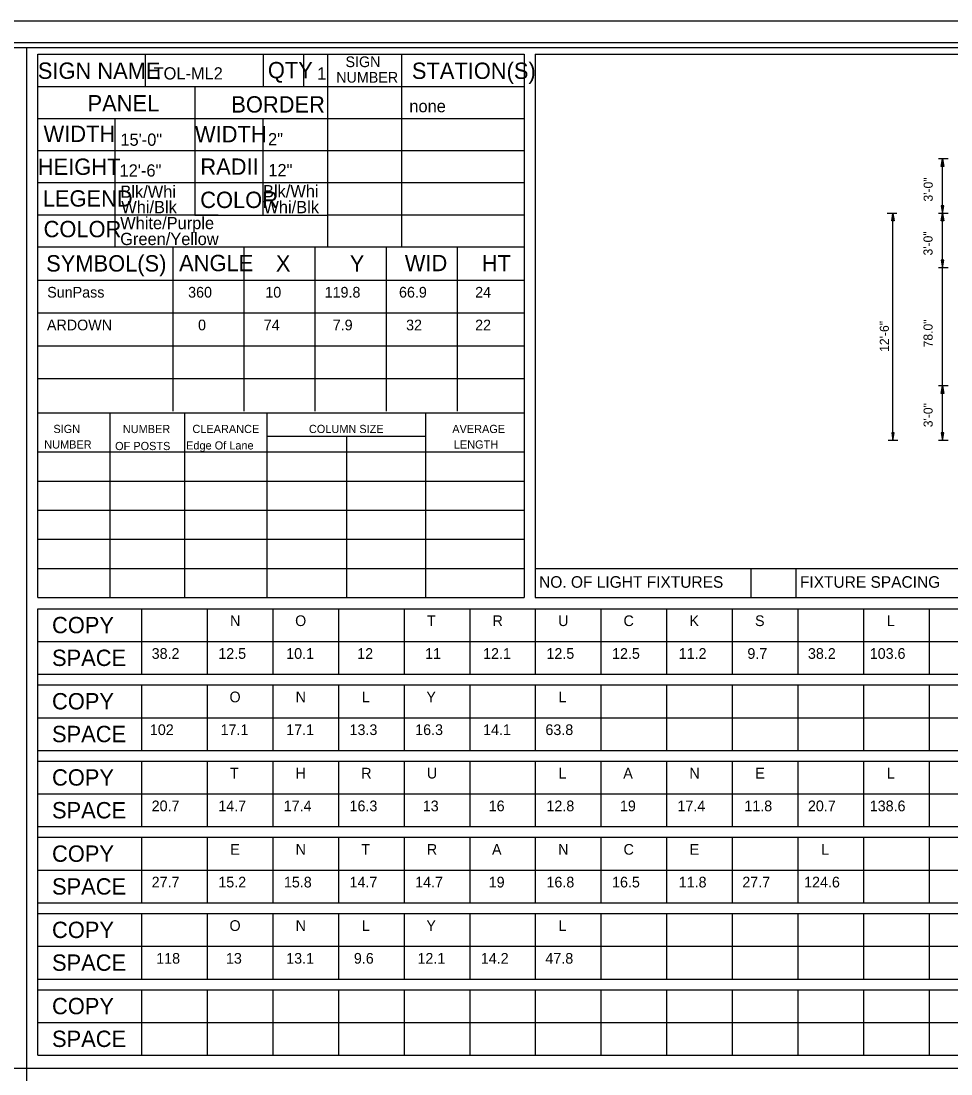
# Model space of a CAD drawing. Extents: x 119523 to 121850, y -23542 to -19972.
# Drawn here: x 120684 to 121298, y -22723 to -22028 of the extents above; entities that cross this region are included whole.
import ezdxf

# ---------------------------------------------------------------- set-up
doc = ezdxf.new("R2010")
doc.units = 0
for name, color, linetype in [('GSDims', 7, 'Continuous'), ('GSSign', 7, 'Continuous'), ('PlotBorder_dp', 7, 'Continuous'), ('SheetBorder_dp', 7, 'Continuous'), ('SheetLinesMisc2_dp', 7, 'Continuous'), ('TextMinor', 7, 'Continuous')]:
    doc.layers.add(name, color=color, linetype=linetype)

msp = doc.modelspace()

# ---------------------------------------------------------------- linework, layer by layer
at = {"layer": 'GSDims'}
for p, q in [((121296.16, -22118.76), (121289.91, -22118.76)), ((121292.41, -22154.76), (121292.41, -22118.76)), ((121296.16, -22118.76), (121296.16, -22118.76)), ((121262.22, -22154.76), (121255.97, -22154.76)), ((121259.74, -22304.76), (121259.74, -22154.76)), ((121296.16, -22154.76), (121289.91, -22154.76)), ((121292.41, -22190.76), (121292.41, -22154.76)), ((121296.16, -22154.76), (121296.16, -22154.76)), ((121296.16, -22190.76), (121289.91, -22190.76)), ((121292.41, -22268.76), (121292.41, -22190.76)), ((121296.16, -22268.76), (121289.91, -22268.76)), ((121292.41, -22304.76), (121292.41, -22268.76)), ((121262.87, -22304.76), (121256.62, -22304.76)), ((121296.16, -22304.76), (121289.91, -22304.76))]:
    msp.add_line(p, q, dxfattribs=at)
for points in [[(121292.41, -22118.76), (121293.25, -22123.76), (121291.58, -22123.76)], [(121292.41, -22154.76), (121293.25, -22149.76), (121291.58, -22149.76)], [(121259.74, -22154.76), (121260.57, -22159.76), (121258.91, -22159.76)], [(121292.41, -22154.76), (121293.25, -22159.76), (121291.58, -22159.76)], [(121292.41, -22190.76), (121293.25, -22185.76), (121291.58, -22185.76)], [(121292.41, -22268.76), (121293.25, -22273.76), (121291.58, -22273.76)], [(121259.74, -22304.76), (121260.57, -22299.76), (121258.91, -22299.76)], [(121292.41, -22304.76), (121293.25, -22299.76), (121291.58, -22299.76)]]:
    msp.add_lwpolyline(points, close=True, dxfattribs=at)
at = {"layer": 'PlotBorder_dp'}
msp.add_lwpolyline([(119522.87, -23522.86), (121850.2, -23522.86), (121850.2, -22027.72), (119522.87, -22027.72)], close=True, dxfattribs=at)
at = {"layer": 'SheetBorder_dp'}
msp.add_line((119600.45, -22041.83), (121772.62, -22041.83), dxfattribs=at)
at = {"layer": 'SheetLinesMisc2_dp'}
for p, q in [((119604.34, -22045.17), (121770.65, -22045.17)), ((120687.5, -22045.17), (120687.5, -23393.68)), ((120694.89, -22408.55), (120694.89, -22049.67)), ((120694.89, -22049.67), (121016.1, -22049.67)), ((120765.7, -22049.67), (120765.7, -22070.86)), ((120843.77, -22049.67), (120843.77, -22070.86)), ((120870.45, -22049.67), (120870.45, -22070.86)), ((120886.34, -22049.67), (120886.34, -22176.86)), ((120935.22, -22049.67), (120935.22, -22176.86)), ((121016.1, -22049.67), (121016.1, -22408.55)), ((121023.51, -22049.66), (121760.29, -22049.66)), ((121023.51, -22049.66), (121023.51, -22408.55)), ((120694.89, -22070.86), (121016.1, -22070.86)), ((120798.7, -22070.86), (120798.7, -22155.88)), ((120694.89, -22092.06), (121016.1, -22092.06)), ((120745.65, -22092.06), (120745.65, -22176.86)), ((120843.5, -22092.29), (120843.5, -22155.88)), ((120694.89, -22113.26), (121016.1, -22113.26)), ((120694.89, -22134.46), (121016.1, -22134.46)), ((120694.89, -22155.66), (120814.02, -22155.66)), ((120798.7, -22155.88), (120886.34, -22155.88)), ((120886.34, -22155.66), (121016.1, -22155.66)), ((120694.89, -22176.86), (121016.1, -22176.86)), ((120784.1, -22177.28), (120784.1, -22285.5)), ((120831.03, -22177.28), (120831.03, -22285.5)), ((120877.96, -22177.28), (120877.96, -22285.5)), ((120924.89, -22177.28), (120924.89, -22285.5)), ((120971.83, -22177.28), (120971.83, -22285.5)), ((120694.96, -22198.92), (121016.1, -22198.92)), ((120694.96, -22220.57), (121016.1, -22220.57)), ((120694.96, -22242.21), (121016.1, -22242.21)), ((120694.96, -22263.86), (121016.1, -22263.86)), ((120694.89, -22286.54), (121016.1, -22286.54)), ((120742.55, -22286.54), (120742.55, -22408.55)), ((120791.83, -22286.54), (120791.83, -22408.55)), ((120846.22, -22286.54), (120846.22, -22408.55)), ((120950.97, -22286.54), (120950.97, -22408.55)), ((120846.22, -22302.06), (120950.9, -22302.06)), ((120898.81, -22302.06), (120898.81, -22408.55)), ((120694.89, -22312.41), (121016.1, -22312.41)), ((120694.89, -22331.63), (121016.1, -22331.63)), ((120694.89, -22350.86), (121016.1, -22350.86)), ((120694.89, -22370.09), (121016.1, -22370.09)), ((120694.89, -22389.32), (121016.1, -22389.32)), ((121023.51, -22389.32), (121760.29, -22389.32)), ((121165.82, -22389.32), (121165.82, -22408.55)), ((121195.64, -22389.32), (121195.64, -22408.55)), ((120694.89, -22408.55), (121016.1, -22408.55)), ((121023.51, -22408.55), (121760.29, -22408.55)), ((120694.9, -22710.93), (120694.9, -22415.94)), ((120694.9, -22415.94), (121760.29, -22415.94)), ((120763.48, -22415.94), (120763.48, -22459.23)), ((120806.83, -22415.94), (120806.83, -22459.23)), ((120850.15, -22415.94), (120850.15, -22459.23)), ((120893.49, -22415.94), (120893.49, -22459.23)), ((120936.85, -22415.94), (120936.85, -22459.23)), ((120980.18, -22415.94), (120980.18, -22459.23)), ((121023.51, -22415.94), (121023.51, -22459.23)), ((121066.86, -22415.94), (121066.86, -22459.23)), ((121110.2, -22415.94), (121110.2, -22459.23)), ((121153.54, -22415.94), (121153.54, -22459.23)), ((121196.89, -22415.94), (121196.89, -22459.23)), ((121240.21, -22415.94), (121240.21, -22459.23)), ((121283.56, -22415.94), (121283.56, -22459.23)), ((120694.9, -22437.58), (121760.29, -22437.58)), ((120694.9, -22459.23), (121760.29, -22459.23)), ((120694.9, -22466.29), (121760.29, -22466.29)), ((120763.48, -22466.29), (120763.48, -22509.57)), ((120806.83, -22466.29), (120806.83, -22509.57)), ((120850.15, -22466.29), (120850.15, -22509.57)), ((120893.49, -22466.29), (120893.49, -22509.57)), ((120936.85, -22466.29), (120936.85, -22509.57)), ((120980.18, -22466.29), (120980.18, -22509.57)), ((121023.51, -22466.29), (121023.51, -22509.57)), ((121066.86, -22466.29), (121066.86, -22509.57)), ((121110.2, -22466.29), (121110.2, -22509.57)), ((121153.54, -22466.29), (121153.54, -22509.57)), ((121196.89, -22466.29), (121196.89, -22509.57)), ((121240.21, -22466.29), (121240.21, -22509.57)), ((121283.56, -22466.29), (121283.56, -22509.57)), ((120694.9, -22487.94), (121760.29, -22487.92)), ((120694.9, -22509.57), (121760.29, -22509.57)), ((120694.9, -22516.62), (121760.29, -22516.62)), ((120763.48, -22516.62), (120763.48, -22559.91)), ((120806.83, -22516.62), (120806.83, -22559.91)), ((120850.15, -22516.62), (120850.15, -22559.91)), ((120893.49, -22516.62), (120893.49, -22559.91)), ((120936.85, -22516.62), (120936.85, -22559.91)), ((120980.18, -22516.62), (120980.18, -22559.91)), ((121023.51, -22516.62), (121023.51, -22559.91)), ((121066.86, -22516.62), (121066.86, -22559.91)), ((121110.2, -22516.62), (121110.2, -22559.91)), ((121153.54, -22516.62), (121153.54, -22559.91)), ((121196.89, -22516.62), (121196.89, -22559.91)), ((121240.21, -22516.62), (121240.21, -22559.91)), ((121283.56, -22516.62), (121283.56, -22559.91)), ((120694.9, -22538.27), (121760.29, -22538.27)), ((120694.9, -22559.91), (121760.29, -22559.91)), ((120694.9, -22566.96), (121760.29, -22566.96)), ((120763.48, -22566.96), (120763.48, -22610.25)), ((120806.83, -22566.96), (120806.83, -22610.25)), ((120850.15, -22566.96), (120850.15, -22610.25)), ((120893.49, -22566.96), (120893.49, -22610.25)), ((120936.85, -22566.96), (120936.85, -22610.25)), ((120980.18, -22566.96), (120980.18, -22610.25)), ((121023.51, -22566.96), (121023.51, -22610.25)), ((121066.86, -22566.96), (121066.86, -22610.25)), ((121110.2, -22566.96), (121110.2, -22610.25)), ((121153.54, -22566.96), (121153.54, -22610.25)), ((121196.89, -22566.96), (121196.89, -22610.25)), ((121240.21, -22566.96), (121240.21, -22610.25)), ((121283.56, -22566.96), (121283.56, -22610.25)), ((120694.9, -22588.61), (121760.29, -22588.61)), ((120694.9, -22610.25), (121760.29, -22610.25)), ((120694.9, -22617.31), (121760.29, -22617.31)), ((120763.48, -22617.31), (120763.48, -22660.59)), ((120806.83, -22617.31), (120806.83, -22660.59)), ((120850.15, -22617.31), (120850.15, -22660.59)), ((120893.49, -22617.31), (120893.49, -22660.59)), ((120936.85, -22617.31), (120936.85, -22660.59)), ((120980.18, -22617.31), (120980.18, -22660.59)), ((121023.51, -22617.31), (121023.51, -22660.59)), ((121066.86, -22617.31), (121066.86, -22660.59)), ((121110.2, -22617.31), (121110.2, -22660.59)), ((121153.54, -22617.31), (121153.54, -22660.59)), ((121196.89, -22617.31), (121196.89, -22660.59)), ((121240.21, -22617.31), (121240.21, -22660.59)), ((121283.56, -22617.31), (121283.56, -22660.59)), ((120694.9, -22638.95), (121760.29, -22638.95)), ((120694.9, -22660.59), (121760.29, -22660.59)), ((120694.9, -22667.65), (121760.29, -22667.65)), ((120763.48, -22667.65), (120763.48, -22710.93)), ((120806.83, -22667.65), (120806.83, -22710.93)), ((120850.15, -22667.65), (120850.15, -22710.93)), ((120893.49, -22667.65), (120893.49, -22710.93)), ((120936.85, -22667.65), (120936.85, -22710.93)), ((120980.18, -22667.65), (120980.18, -22710.93)), ((121023.51, -22667.65), (121023.51, -22710.93)), ((121066.86, -22667.65), (121066.86, -22710.93)), ((121110.2, -22667.65), (121110.2, -22710.93)), ((121153.54, -22667.65), (121153.54, -22710.93)), ((121196.89, -22667.65), (121196.89, -22710.93)), ((121240.21, -22667.65), (121240.21, -22710.93)), ((121283.56, -22667.65), (121283.56, -22710.93)), ((120694.9, -22689.28), (121760.29, -22689.28)), ((120694.9, -22710.93), (121760.29, -22710.93)), ((119604.34, -22719.43), (121770.65, -22719.43))]:
    msp.add_line(p, q, dxfattribs=at)

# ---------------------------------------------------------------- texts
at = {"layer": 'GSDims'}
for s, p in [('3\'-0"', (121286.01, -22146.97)), ('3\'-0"', (121285.9, -22182.62)), ('12\'-6"', (121257.04, -22246.27)), ('78.0"', (121285.93, -22243.31)), ('3\'-0"', (121285.97, -22296.08))]:
    msp.add_text(s, height=6, rotation=90, dxfattribs=at).set_placement(p)
at = {"layer": 'GSSign'}
for s, height, p in [('TOL-ML2', 8.099, (120771.34, -22066.33)), ('1', 8.1, (120879.45, -22066.35)), ('none', 8.099, (120940.3, -22087.96)), ('15\'-0"', 8.099, (120749.43, -22110.12)), ('2"', 8.099, (120846.95, -22109.81)), ('12\'-6"', 8.099, (120748.88, -22130.46)), ('12"', 8.099, (120847.17, -22130.24)), ('Blk/Whi', 8.099, (120749.45, -22144.46)), ('Blk/Whi', 8.099, (120843.65, -22144.18)), ('Whi/Blk', 8.099, (120750.01, -22154.67)), ('Whi/Blk', 8.099, (120843.89, -22154.66)), ('White/Purple', 8.099, (120749.31, -22165.21)), ('Green/Yellow', 8.099, (120749.31, -22175.71)), ('SunPass', 7.058, (120701.1, -22210.4)), ('360', 7.058, (120794.19, -22210.4)), ('10', 7.058, (120845.16, -22210.4)), ('119.8', 7.058, (120884.36, -22210.4)), ('66.9', 7.058, (120933.47, -22210.4)), ('24', 7.058, (120983.78, -22210.4)), ('ARDOWN', 7.058, (120700.91, -22232.04)), ('0', 7.06, (120800.72, -22232.04)), ('74', 7.058, (120844.12, -22232.04)), ('7.9', 7.058, (120889.71, -22232.04)), ('32', 7.058, (120938.15, -22232.04)), ('22', 7.058, (120983.76, -22232.04)), ('N', 7.06, (120821.84, -22427.41)), ('O', 7.06, (120864.85, -22427.41)), ('T', 7.06, (120951.89, -22427.41)), ('R', 7.06, (120995.24, -22427.41)), ('U', 7.06, (121038.59, -22427.41)), ('C', 7.06, (121081.77, -22427.41)), ('K', 7.06, (121125.28, -22427.41)), ('S', 7.06, (121168.63, -22427.41)), ('L', 7.06, (121255.67, -22427.41)), ('38.2', 7.058, (120770.09, -22449.06)), ('12.5', 7.058, (120814.11, -22449.06)), ('10.1', 7.058, (120858.97, -22449.06)), ('12', 7.058, (120905.85, -22449.06)), ('11', 7.058, (120950.71, -22449.06)), ('12.1', 7.058, (120989.02, -22449.06)), ('12.5', 7.058, (121030.86, -22449.06)), ('12.5', 7.058, (121074.2, -22449.06)), ('11.2', 7.058, (121118.23, -22449.06)), ('9.7', 7.058, (121163.59, -22449.06)), ('38.2', 7.058, (121203.58, -22449.06)), ('103.6', 7.058, (121244.41, -22449.06)), ('O', 7.06, (120821.5, -22477.76)), ('N', 7.06, (120865.19, -22477.76)), ('L', 7.06, (120908.87, -22477.76)), ('Y', 7.06, (120951.55, -22477.76)), ('L', 7.06, (121038.92, -22477.76)), ('102', 7.058, (120768.91, -22499.4)), ('17.1', 7.058, (120815.62, -22499.4)), ('17.1', 7.058, (120858.97, -22499.4)), ('13.3', 7.058, (120900.81, -22499.4)), ('16.3', 7.058, (120944.16, -22499.4)), ('14.1', 7.058, (120989.02, -22499.4)), ('63.8', 7.058, (121030.18, -22499.4)), ('T', 7.06, (120821.84, -22528.11)), ('H', 7.06, (120865.19, -22528.11)), ('R', 7.06, (120908.54, -22528.11)), ('U', 7.06, (120951.89, -22528.11)), ('L', 7.06, (121038.92, -22528.11)), ('A', 7.06, (121081.6, -22528.11)), ('N', 7.06, (121125.28, -22528.11)), ('E', 7.06, (121168.8, -22528.11)), ('L', 7.06, (121255.67, -22528.11)), ('20.7', 7.058, (120770.09, -22549.75)), ('14.7', 7.058, (120814.11, -22549.75)), ('17.4', 7.058, (120857.29, -22549.75)), ('16.3', 7.058, (120900.81, -22549.75)), ('13', 7.058, (120949.2, -22549.75)), ('16', 7.058, (120992.72, -22549.75)), ('12.8', 7.058, (121030.86, -22549.75)), ('19', 7.058, (121079.41, -22549.75)), ('17.4', 7.058, (121117.39, -22549.75)), ('11.8', 7.058, (121161.58, -22549.75)), ('20.7', 7.058, (121203.58, -22549.75)), ('138.6', 7.058, (121244.41, -22549.75)), ('E', 7.06, (120822.01, -22578.45)), ('N', 7.06, (120865.19, -22578.45)), ('T', 7.06, (120908.54, -22578.45)), ('R', 7.06, (120951.89, -22578.45)), ('A', 7.06, (120994.9, -22578.45)), ('N', 7.06, (121038.59, -22578.45)), ('C', 7.06, (121081.77, -22578.45)), ('E', 7.06, (121125.45, -22578.45)), ('L', 7.06, (121212.32, -22578.45)), ('27.7', 7.058, (120770.09, -22600.09)), ('15.2', 7.058, (120814.11, -22600.09)), ('15.8', 7.058, (120857.46, -22600.09)), ('14.7', 7.058, (120900.81, -22600.09)), ('14.7', 7.058, (120944.16, -22600.09)), ('19', 7.058, (120992.72, -22600.09)), ('16.8', 7.058, (121030.86, -22600.09)), ('16.5', 7.058, (121074.2, -22600.09)), ('11.8', 7.058, (121118.23, -22600.09)), ('27.7', 7.058, (121160.23, -22600.09)), ('124.6', 7.058, (121201.06, -22600.09)), ('O', 7.06, (120821.5, -22628.8)), ('N', 7.06, (120865.19, -22628.8)), ('L', 7.06, (120908.87, -22628.8)), ('Y', 7.06, (120951.55, -22628.8)), ('L', 7.06, (121038.92, -22628.8)), ('118', 7.058, (120773.11, -22650.44)), ('13', 7.058, (120819.15, -22650.44)), ('13.1', 7.058, (120858.97, -22650.44)), ('9.6', 7.058, (120903.66, -22650.44)), ('12.1', 7.058, (120945.67, -22650.44)), ('14.2', 7.058, (120987.51, -22650.44)), ('47.8', 7.058, (121030.18, -22650.44))]:
    msp.add_text(s, height=height, dxfattribs=at).set_placement(p)
at = {"layer": 'TextMinor'}
for s, height, p in [('SIGN NAME', 10.799, (120694.89, -22065.9)), ('QTY', 10.799, (120846.85, -22065.54)), ('SIGN', 7.058, (120898.14, -22058.16)), ('STATION(S)', 10.799, (120941.96, -22065.96)), ('NUMBER', 7.058, (120892, -22068.43)), ('PANEL', 10.799, (120727.73, -22087.43)), ('BORDER', 10.799, (120822.71, -22088.17)), ('WIDTH', 10.799, (120698.7, -22107.61)), ('WIDTH', 10.799, (120798.7, -22107.83)), ('HEIGHT', 10.799, (120694.89, -22129.34)), ('RADII', 10.799, (120802.25, -22129.3)), ('LEGEND', 10.799, (120698.14, -22150.31)), ('COLOR', 10.799, (120802.16, -22151.22)), ('COLOR', 10.799, (120698.7, -22170.53)), ('SYMBOL(S)', 10.799, (120700.42, -22193.19)), ('ANGLE', 10.799, (120788.22, -22192.97)), ('X', 10.8, (120852.15, -22193.19)), ('Y', 10.8, (120900.95, -22193.19)), ('WID', 10.799, (120937.29, -22192.97)), ('HT', 10.799, (120988.17, -22193.17)), ('SIGN', 5.4, (120705.19, -22299.86)), ('NUMBER', 5.4, (120751.03, -22299.92)), ('CLEARANCE', 5.4, (120797.01, -22299.88)), ('COLUMN SIZE', 5.3996, (120873.96, -22299.88)), ('AVERAGE', 5.4, (120968.66, -22299.88)), ('NUMBER', 5.4, (120699.14, -22310.13)), ('OF POSTS', 5.4, (120745.93, -22311.15)), ('Edge Of Lane', 5.3996, (120792.85, -22310.75)), ('LENGTH', 5.4, (120969.68, -22310.13)), ('NO. OF LIGHT FIXTURES', 7.6529, (121025.99, -22402.11)), ('FIXTURE SPACING', 7.6529, (121198.29, -22402.11)), ('COPY', 10.799, (120704.26, -22432.14)), ('SPACE', 10.799, (120704.26, -22453.78)), ('COPY', 10.799, (120704.26, -22482.47)), ('SPACE', 10.799, (120704.26, -22504.11)), ('COPY', 10.799, (120704.26, -22532.81)), ('SPACE', 10.799, (120704.26, -22554.46)), ('COPY', 10.799, (120704.26, -22583.15)), ('SPACE', 10.799, (120704.26, -22604.8)), ('COPY', 10.799, (120704.26, -22633.5)), ('SPACE', 10.799, (120704.26, -22655.15)), ('COPY', 10.799, (120704.26, -22683.84)), ('SPACE', 10.799, (120704.26, -22705.48))]:
    msp.add_text(s, height=height, dxfattribs=at).set_placement(p)

doc.saveas('drawing.dxf')
